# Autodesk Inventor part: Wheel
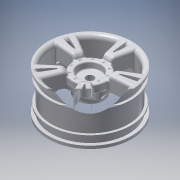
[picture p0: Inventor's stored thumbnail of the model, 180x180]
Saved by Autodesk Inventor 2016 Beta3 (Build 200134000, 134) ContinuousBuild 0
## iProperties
Shininess: 54.0
Length Units: 11272
Angle Units: 11279
Time Units: 11290
Mass Units: 11286
Length Display Precision: 4
Angle Display Precision: 2
Compacted: True
Company: Autodesk
Created: 2000-05
Part Number: Wheel
Project: Inventor Samples
User Status: IN PROGRESS
Document SubType Name: Modeling
Designer: Autodesk, Inc.
Density: 2.71 g/cm^3
Material: Aluminum-6061
Mass: 26.0183 g
Surface Area: 145.445 cm^2
Volume: 9.60086 cm^3
Appearance: Light Grey
Density: 0.0
Volumn: 0.0
Area: 0.0
PropertySet Name: Model Information
Control State: 0
Master: False
Checked Out: False
Author: Autodesk, Inc.
Revision Number: A
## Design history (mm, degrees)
node "Revolution1" dims "d2" = 90 deg
  sketch "Sketch2"
    geometry: L1 (-26.543, 0)-(0, 0); L2 (0, 0)-(0, 25.971); L3 (0, 25.971)-(-26.543, 25.971); L4 (-26.543, 0)-(-26.543, 25.971); L5 (-31.852, 0)-(5.309, 0) reference; 1 further point
    constraints: 8 end point, 2 parallel, 1 collinear, 1 horizontal, 1 perpendicular, 1 point on line
    dimensions: "d0" = 51.943 diameter of L3 L1; "d1" = 26.543 distance between parallel lines of L4 L2
node "Revolution2" dims "d6" = 90 deg
  sketch "Sketch3"
    geometry: L1 (-31.852, 0)-(5.309, 0) reference; L2 (0, -25.971)-(0, 25.971) reference; L3 (-26.543, 25.971)-(0, 25.971) reference; L4 (-1.778, 25.971)-(-1.778, 23.94); L5 (-1.778, 23.94)-(-24.765, 23.94); L6 (-24.765, 23.94)-(-24.765, 25.971); L7 (-26.543, -25.971)-(-26.543, 25.971) reference
    constraints: 6 end point, 2 perpendicular, 2 point on line, 1 parallel
    dimensions: "d3" = 47.879 diameter of L5 L1; "d4" = 1.778 distance between parallel lines of L2 L4; "d5" = 1.778 distance between parallel lines of L6 L7 (= d4)
node "Revolution3" dims "d12" = 90 deg
  sketch "Sketch4"
    geometry: L1 (-24.765, 23.94)-(-1.778, 23.94) reference; L2 (0, -25.971)-(0, 25.971) reference; L3 (-26.543, -25.971)-(-26.543, 25.971) reference; L4 (-31.852, 0)-(5.309, 0) reference; L5 (-20.701, 23.94)-(-20.701, 25.4); L6 (-20.701, 25.4)-(-19.558, 25.4); L7 (-19.558, 25.4)-(-19.558, 23.94); L8 (-6.985, 23.94)-(-6.985, 25.4); L9 (-6.985, 25.4)-(-5.842, 25.4); L10 (-5.842, 25.4)-(-5.842, 23.94)
    constraints: 12 end point, 4 perpendicular, 4 point on line, 2 parallel, 1 collinear
    dimensions: "d7" = 1.143 distance between parallel lines of L7 L5 (= d8); "d8" = 1.143 distance between parallel lines of L10 L8; "d9" = 6.985 distance between parallel lines of L2 L8; "d10" = 6.985 distance between parallel lines of L3 L7; "d11" = 50.8 diameter of L9.end L4
node "Extrusion1" dims "d14" = 11.811, "d15" = 0
  sketch "Sketch5"
    geometry: C1 r 25.971 at (0, 0) reference; C2 r 22.86 at (0, 0)
    constraints: 1 centre point, 1 coincident
    dimensions: "d13" = 45.72 diameter of C2
node "Extrusion2" dims "d17" = 11.811, "d18" = 0
  sketch "Sketch6"
    geometry: C1 r 22.86 at (0, 0) reference; C2 r 8.382 at (0, 0)
    constraints: 1 centre point, 1 coincident
    dimensions: "d16" = 16.764 diameter of C2
node "Extrusion3" dims "d19" = 6.731, "d20" = 0
  sketch "Sketch7"
    geometry: C1 r 8.382 at (0, 0) reference
node "Fillet4" dims "d40" = 2.54
node "Extrusion5" dims "d46" = 8.89 (computed from d19), "d47" = 0
  sketch "Sketch10"
    geometry: L1 (0, 0)-(0, 25.971); L2 (-6.072, 24.664)-(-2.989, 11.822); L3 (6.072, 24.664)-(2.989, 11.822); A1 r 25.4 centre (0, 0) between (1.27, 25.368) and (-1.27, 25.368) reference; A2 r 57.15 centre (-55.876, 24.699) between (0, 12.7) and (1.27, 25.368); A3 r 57.15 centre (55.876, 24.699) between (-1.27, 25.368) and (0, 12.7); A4 r 8.382 centre (0, 0) between (-4.859, 6.83) and (4.859, 6.83) reference; A5 r 4.763 centre (-7.62, 10.71) between (-4.859, 6.83) and (-2.989, 11.822); A6 r 4.763 centre (7.62, 10.71) between (2.989, 11.822) and (4.859, 6.83); 1 further point
    constraints: 14 point on circle, 6 end point, 4 centre point, 4 tangent, 3 horizontal alignment, 2 equal radius, 1 point on line, 1 vertical, 1 vertical alignment, 1 other
    dimensions: "d41" = 12.7 distance of A2.start point (0, 0); "d42" = 2.54 distance of A1.start A1.end; "d43" = 57.15 radius of A2; "d44" = 27 deg angle of L3 L2; "d45" = 4.7625 radius of A5; "d51" = 15.24 distance of A6.centre A5.centre
node "Fillet6" dims "d59" = 0.39687
node "Circular Pattern2" dims "d48" = 50 (= Spokes), "d50" = 360 deg
node "Revolution5" dims "d53" = 90 deg
  sketch "Sketch11"
    geometry: L1 (-24.765, 23.906)-(-20.701, 23.906) reference; L2 (-19.558, 23.94)-(-6.985, 23.94) reference; L3 (-20.701, 25.4)-(-19.558, 25.4) reference; L4 (-26.543, 25.971)-(-24.765, 25.971) reference; L5 (-26.543, 25.971)-(-26.543, 27.241); L6 (-26.543, 27.241)-(-6.985, 27.242); L7 (-6.985, 27.242)-(-6.985, 23.94); L8 (-19.558, 25.4)-(-19.558, 23.94); L9 (-20.701, 25.4)-(-20.701, 23.906); L10 (-24.765, 25.971)-(-24.765, 23.906); L11 (-30.455, 0)-(-3.073, 0) reference
    constraints: 12 end point, 4 parallel, 2 perpendicular
    dimensions: "d52" = 1.27 distance of L4.start L5.end
node "Revolution6" dims "d57" = 90 deg
  sketch "Sketch12"
    geometry: L1 (-26.543, -25.971)-(-26.543, 25.971) reference; L2 (-19.812, 8.382)-(-26.543, 8.382) reference; L3 (-28.689, 0)-(-17.974, 0) reference; L4 (-19.812, 0)-(-19.812, 8.382); L5 (-23.645, 10.172)-(-21.261, 9.963); A1 r 3.175 centre (-23.368, 13.335) between (-26.543, 13.335) and (-23.645, 10.172); A2 r 1.587 centre (-21.399, 8.382) between (-19.812, 8.382) and (-21.261, 9.963)
    constraints: 4 end point, 4 point on circle, 4 tangent, 2 centre point, 2 point on line, 1 perpendicular
    dimensions: "d54" = 3.175 radius of A1; "d55" = 1.5875 radius of A2; "d56" = 85 deg angle of L4 L5
node "Fillet5" dims "d58" = 5.08
workaxis "Work Axis2"
workplane "Work Plane3"
  workpoint "Work Point3"
  workpoint "Work Point4"
  workpoint "Work Point5"
node "Revolution8" dims "d97" = 90 deg
  sketch "Sketch17"
    geometry: L1 (-1.449, 9.963)-(-3.833, 10.172) reference; L2 (0, 6.732)-(-3.833, 7.067); L3 (25.121, 0)-(-12.045, 0) reference; L4 (-3.833, 7.067)-(-3.833, 10.641); L5 (-3.833, 10.641)-(1.27, 10.641); L6 (1.27, 10.641)-(1.27, 6.732); L7 (1.27, 6.732)-(0, 6.732); L8 (0, -2.511)-(0, 6.732) reference; A1 r 1.587 centre (-1.588, 8.382) between (0, 8.382) and (-1.449, 9.963) reference
    constraints: 10 end point, 3 parallel, 2 perpendicular
    dimensions: "d93" = 1.27 distance between parallel lines of L6 L8
node "Fillet14" dims "d100" = 1.5875
node "Fillet15" dims "d101" = 1.5875
node "Fillet16" dims "d102" = 0.8128
node "Fillet17" dims "d103" = 0.8128
node "Fillet18" dims "d104" = 0.8128
node "Extrusion7" dims "d71" = 5.08, "d72" = 0
  sketch "Sketch14"
    geometry: L1 (-6.032, 3.483)-(-6.032, -3.483); L2 (-6.032, -3.483)-(0, -6.966); L3 (0, -6.966)-(6.032, -3.483); L4 (6.032, -3.483)-(6.032, 3.483); L5 (6.032, 3.483)-(0, 6.966); L6 (0, 6.966)-(-6.032, 3.483); C1 r 8.382 at (0, 0) reference; C2 r 6.032 at (0, 0)
    constraints: 12 end point, 6 tangent, 4 equal length, 2 vertical, 1 centre point, 1 coincident
    dimensions: "d70" = 12.065 distance between parallel lines of L4 L1
node "Fillet9" dims "d73" = 3.175
node "Extrusion8" dims "d79" = 25.4, "d80" = 0
  sketch "Sketch15"
    geometry: L1 (-3.285, 13.055)-(-4.738, 19.106) reference; L2 (-2.989, 11.822)-(-3.285, 13.055) reference; L3 (4.738, 19.106)-(3.285, 13.055) reference; L4 (2.989, 11.822)-(3.285, 13.055) reference; L5 (0, 0)-(-4.166, 22.477); L6 (0, 0)-(4.166, 22.477); L7 (-2.911, 22.674)-(-1.198, 13.431); L8 (1.198, 13.431)-(2.911, 22.674); L9 (0, 0)-(0, 13.652); C1 r 25.971 at (0, 0) reference; A1 r 22.86 centre (0, 0) between (-4.166, 22.477) and (4.166, 22.477) reference; A2 r 57.15 centre (55.876, 24.699) between (-1.051, 19.657) and (-0.391, 14.691) reference; A3 r 57.15 centre (-55.876, 24.699) between (0.391, 14.691) and (1.051, 19.657) reference; A4 r 1.218 centre (0, 13.652) between (-1.198, 13.431) and (1.198, 13.431); A5 r 2.488 centre (0, 13.652) between (-2.446, 13.199) and (2.446, 13.199); 4 further points
    constraints: 10 end point, 8 point on circle, 2 centre point, 2 parallel, 2 point on line, 2 tangent, 1 concentric, 1 vertical
    dimensions: "d74" = 1.27 distance between parallel lines of L7 L5; "d75" = 1.27 distance between parallel lines of L6 L8 (= d74); "d76" = 13.6525 distance of A1.centre L9.end; "d77" = 21 deg angle of L8 L7; "d78" = 1.27 radial gap between concentric circles of A4 A5 (= d75)
node "Circular Pattern3" dims "d81" = 50 (= Spokes), "d83" = 360 deg
node "Extrusion6" dims "d68" = 2.159, "d69" = 0
  sketch "Sketch13"
    geometry: C1 r 2.381 at (0, 0); C2 r 23.94 at (0, 0) reference
    constraints: 1 centre point, 1 concentric
    dimensions: "d67" = 4.7625 diameter of C1
workplane "Work Plane4"
node "Extrusion9" dims "d108" = 25.4, "d109" = 20 deg
  sketch "Sketch18" dims "d106" = 17.78
    geometry: L1 (0, 36.36)-(0, -36.36) reference; C1 r 2.381 at (0, 0) reference; C2 r 0.635 at (0, 8.89); 1 further point
    constraints: 1 centre point, 1 coincident, 1 point on line, 1 vertical alignment, 2 other
    dimensions: "d107" = 1.27 diameter of C2
node "Fillet19" dims "d110" = 0.127
node "Circular Pattern4" dims "d111" = 100, "d113" = 360 deg
node "Fillet20" dims "d114" = 0.8128
node "Fillet21" dims "d115" = 0.8128
node "Fillet22" dims "d116" = 0.8128
body "Solid1"
other parameters: "d95" = 5 deg (derived), "d96" = 22.88399 (derived), "d105" = -0.381
